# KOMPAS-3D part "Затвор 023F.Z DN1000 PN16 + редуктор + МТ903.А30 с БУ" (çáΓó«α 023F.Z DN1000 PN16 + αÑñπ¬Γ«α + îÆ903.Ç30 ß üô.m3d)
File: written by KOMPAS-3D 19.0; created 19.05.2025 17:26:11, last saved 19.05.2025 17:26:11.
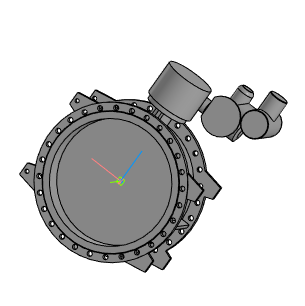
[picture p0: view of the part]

Document properties: Полное имя файла: Затвор 023F.Z DN1000 PN16 + редуктор + МТ903.А30 с БУ.a3d

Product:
- Part/product: Затвор 023F.Z DN1000 PN16 + редуктор + МТ903.А30 с БУ
    Масса: 1889.14

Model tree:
1. Операция без истории:1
